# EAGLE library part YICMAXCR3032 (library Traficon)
XILINX XCR3032XL
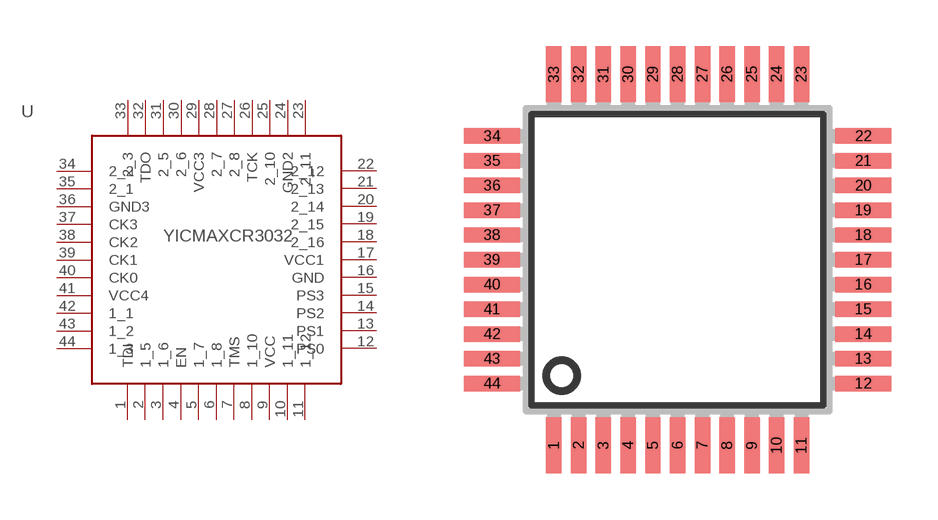
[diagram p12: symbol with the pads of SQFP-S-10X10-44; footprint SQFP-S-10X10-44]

Designator prefix U

## YICMAXCR3032  [SQFP-S-10X10-44]
1  TDI
2  1_5
3  1_6
4  EN
5  1_7
6  1_8
7  TMS
8  1_10
9  VCC  pas
10  1_11
11  1_12
12  PS0
13  PS1
14  PS2
15  PS3
16  GND  pas
17  VCC1  pas
18  2_16
19  2_15
20  2_14
21  2_13
22  2_12
23  2_11
24  GND2  pas
25  2_10
26  TCK
27  2_8
28  2_7
29  VCC3  pas
30  2_6
31  2_5
32  TDO
33  2_3
34  2_2
35  2_1
36  GND3  pas
37  CK3
38  CK2
39  CK1
40  CK0
41  VCC4  pas
42  1_1
43  1_2
44  1_3

## Footprint SQFP-S-10X10-44 (pad centres in mm)
QFP44 shrink quad flat pack, square
smd 0.5 x 1.8: 1 -4,-6; 2 -3.2,-6; 3 -2.4,-6; 4 -1.6,-6; 5 -0.8,-6; 6 0,-6; 7 0.8,-6; 8 1.6,-6; 9 2.4,-6; 10 3.2,-6; 11 4,-6; 23 4,6; 24 3.2,6; 25 2.4,6; 26 1.6,6; 27 0.8,6; 28 0,6; 29 -0.8,6; 30 -1.6,6; 31 -2.4,6; 32 -3.2,6; 33 -4,6
smd 1.8 x 0.5: 12 6,-4; 13 6,-3.2; 14 6,-2.4; 15 6,-1.6; 16 6,-0.8; 17 6,0; 18 6,0.8; 19 6,1.6; 20 6,2.4; 21 6,3.2; 22 6,4; 34 -6,4; 35 -6,3.2; 36 -6,2.4; 37 -6,1.6; 38 -6,0.8; 39 -6,0; 40 -6,-0.8; 41 -6,-1.6; 42 -6,-2.4; 43 -6,-3.2; 44 -6,-4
